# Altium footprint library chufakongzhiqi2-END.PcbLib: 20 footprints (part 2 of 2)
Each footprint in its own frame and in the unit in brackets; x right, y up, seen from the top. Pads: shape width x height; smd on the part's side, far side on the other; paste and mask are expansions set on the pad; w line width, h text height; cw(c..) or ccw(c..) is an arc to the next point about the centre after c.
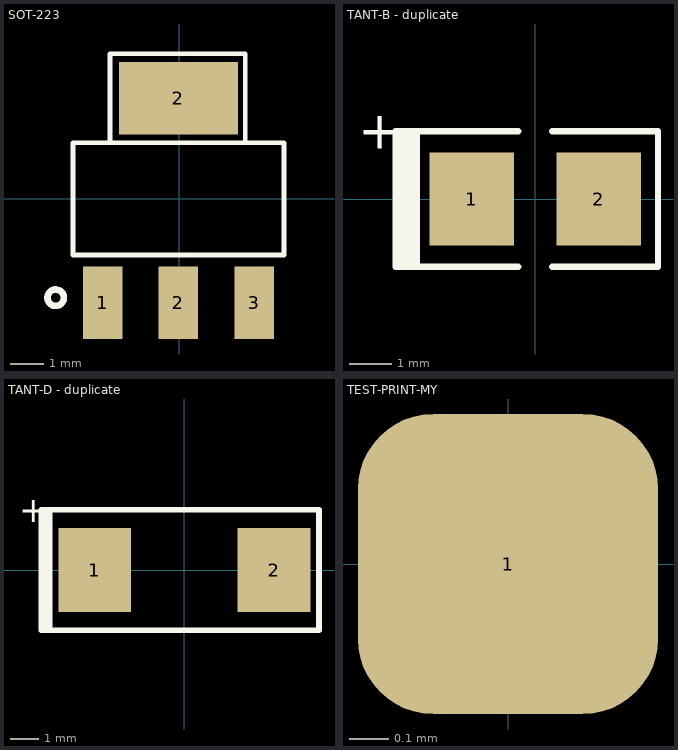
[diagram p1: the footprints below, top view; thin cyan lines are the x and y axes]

## SOT-223 [mm] "LM1117-5.0-3.3-2.8-1.8-ADJ"
pads (4):
  rect 1.2x2.2 smd: 1(-2.326,-3.153) 2(-0.026,-3.153) 3(2.274,-3.153)
  rect 3.6x2.2 smd: 2(-0.026,3.047)
Top Overlay:
  circle w0.2: c-3.75,-3 r0.25
  lines w0.15: -2.1,1.7 -2.1,4.4 2,4.4 2,1.7 ; -3.226,-1.7 -3.226,1.7 3.174,1.7 3.174,-1.7 -0.173,-1.7 -3.226,-1.7

## TANT-B - duplicate [mm]
pads (2):
  rect 2x2.2 smd: 1(-1.5,0) 2(1.5,0)
Top Overlay:
  lines w0.15: -3,-1.4 -3,1.4 -3.1,1.4 -3.1,-1.5 -2.9,-1.5 -2.9,1.5 -3.2,1.5 -3.2,-1.6 -2.8,-1.6 -2.8,1.6 ; -0.4,-1.6 -3.3,-1.6 -3.3,1.6 -0.4,1.6 ; 0.4,-1.6 2.9,-1.6 2.9,1.6 0.4,1.6
  text "+" at -4.187,1.188 h0.89

## TANT-D - duplicate [mm]
pads (2):
  rect 2.6x3 smd: 1(-3.2,0) 2(3.2,0)
Top Overlay:
  lines w0.2: -4.95,-2.15 -4.95,2.15 ; -4.8,-2.15 -4.8,2.15 ; -4.8,-2.15 -4.1,-2.15 4.8,-2.15 4.8,2.15 -4.8,2.15 ; -4.8,-2.15 -5.1,-2.15 -5.1,2.15 -4.8,2.15
  text "+" at -5.9,1.7 h0.89

## TEST-PRINT-MY [mil]
pads (1):
  rrect50% 30x30 smd: 1(0,0)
